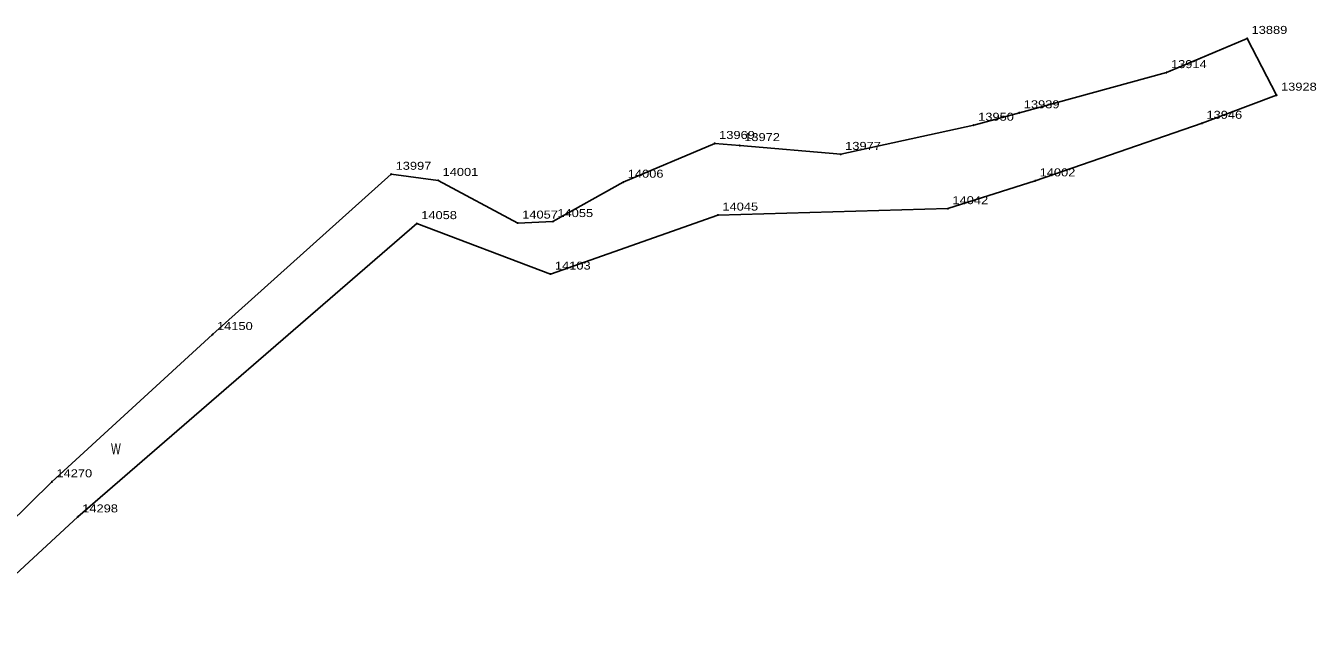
# Model space of a CAD drawing. Extents: x 4640203 to 4641683, y 5358965 to 5360242.
# Drawn here: x 4641537.8 to 4641682.9, y 5359873.4 to 5359943 of the extents above; entities that cross this region are included whole.
import ezdxf

# ---------------------------------------------------------------- set-up
doc = ezdxf.new("R2010")
doc.units = 0
doc.header["$LTSCALE"] = 0.36
for name, color, linetype, lineweight in [('25', 7, 'Continuous', 25), ('27', 7, 'Continuous', 25), ('8', 7, 'Continuous', 25)]:
    doc.layers.add(name, color=color, linetype=linetype, lineweight=lineweight)
doc.layers.add('26', color=7, linetype='Continuous')

msp = doc.modelspace()

# ---------------------------------------------------------------- linework, layer by layer
at = {"layer": '25'}
msp.add_lwpolyline([(4641528.14, 5359873.41), (4641543.66, 5359887.74), (4641581.77, 5359920.74), (4641596.8, 5359915.06), (4641615.63, 5359921.7), (4641641.49, 5359922.42), (4641651.29, 5359925.55), (4641670.05, 5359932.03), (4641678.43, 5359935.19), (4641675.12, 5359941.58), (4641666.06, 5359937.73), (4641649.51, 5359933.21), (4641644.38, 5359931.81), (4641629.43, 5359928.53), (4641618.08, 5359929.52), (4641615.26, 5359929.76), (4641604.99, 5359925.4), (4641597.08, 5359920.97), (4641593.12, 5359920.8), (4641584.17, 5359925.6), (4641578.89, 5359926.29), (4641558.81, 5359908.26), (4641540.76, 5359891.69), (4641525.71, 5359876.89)], dxfattribs=at)
at = {"layer": '27'}
msp.add_lwpolyline([(4641528.14, 5359873.41), (4641543.66, 5359887.74), (4641581.77, 5359920.74), (4641596.8, 5359915.06), (4641615.63, 5359921.7), (4641641.49, 5359922.42), (4641651.29, 5359925.55), (4641670.05, 5359932.03), (4641678.43, 5359935.19), (4641675.12, 5359941.58), (4641668.82, 5359938.9), (4641666.06, 5359937.73), (4641649.51, 5359933.21), (4641644.38, 5359931.81), (4641629.43, 5359928.53), (4641618.08, 5359929.52), (4641615.26, 5359929.76), (4641604.99, 5359925.4), (4641597.08, 5359920.97), (4641593.12, 5359920.8), (4641584.17, 5359925.6), (4641578.89, 5359926.29), (4641558.81, 5359908.26), (4641540.76, 5359891.69), (4641525.71, 5359876.89)], dxfattribs=at)
at = {"layer": '8'}
for centre in [(4641675.12, 5359941.58), (4641666.06, 5359937.73), (4641678.43, 5359935.19), (4641649.51, 5359933.21), (4641644.38, 5359931.81), (4641670.05, 5359932.03), (4641615.26, 5359929.76), (4641618.08, 5359929.52), (4641629.43, 5359928.53), (4641578.89, 5359926.29), (4641584.17, 5359925.6), (4641604.99, 5359925.4), (4641651.29, 5359925.55), (4641641.49, 5359922.42), (4641581.77, 5359920.74), (4641593.12, 5359920.8), (4641597.08, 5359920.97), (4641615.63, 5359921.7), (4641596.8, 5359915.06), (4641558.81, 5359908.26), (4641540.76, 5359891.69), (4641543.66, 5359887.74)]:
    msp.add_circle(centre, 0.045, dxfattribs=at)

# ---------------------------------------------------------------- texts
at = {"layer": '26', "width": 0.7}
msp.add_text('W', height=1.25, dxfattribs=at).set_placement((4641547.39, 5359894.78))
at = {"layer": '8', "width": 1.2}
for s, p in [('13889', (4641675.62, 5359942.08)), ('13914', (4641666.56, 5359938.23)), ('13928', (4641678.93, 5359935.69)), ('13939', (4641650.01, 5359933.71)), ('13950', (4641644.88, 5359932.31)), ('13946', (4641670.55, 5359932.53)), ('13969', (4641615.76, 5359930.26)), ('13972', (4641618.58, 5359930.02)), ('13977', (4641629.93, 5359929.03)), ('13997', (4641579.39, 5359926.79)), ('14001', (4641584.67, 5359926.1)), ('14006', (4641605.49, 5359925.9)), ('14002', (4641651.79, 5359926.05)), ('14042', (4641641.99, 5359922.92)), ('14057', (4641593.62, 5359921.3)), ('14055', (4641597.58, 5359921.47)), ('14045', (4641616.13, 5359922.2)), ('14058', (4641582.27, 5359921.24)), ('14103', (4641597.3, 5359915.56)), ('14150', (4641559.31, 5359908.76)), ('14270', (4641541.26, 5359892.19)), ('14298', (4641544.16, 5359888.24))]:
    msp.add_text(s, height=0.9, dxfattribs=at).set_placement(p)

doc.saveas('drawing.dxf')
